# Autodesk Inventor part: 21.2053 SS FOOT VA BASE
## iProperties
Created: 2011-11
Part Number: 21.2053 SS FOOT VA BASE
Material: Stainless Steel
Document SubType Name: Modeling
Designer: Administrator
Mass: 60.855 g
Surface Area: 43.5687 cm^2
Volume: 7.53157 cm^3
Density: 8.08 g/cm^3
Author: Administrator
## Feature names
1. Base1
2. Shell1
3. Extrusion1
